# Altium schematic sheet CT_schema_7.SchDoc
size 391 x 238 mm
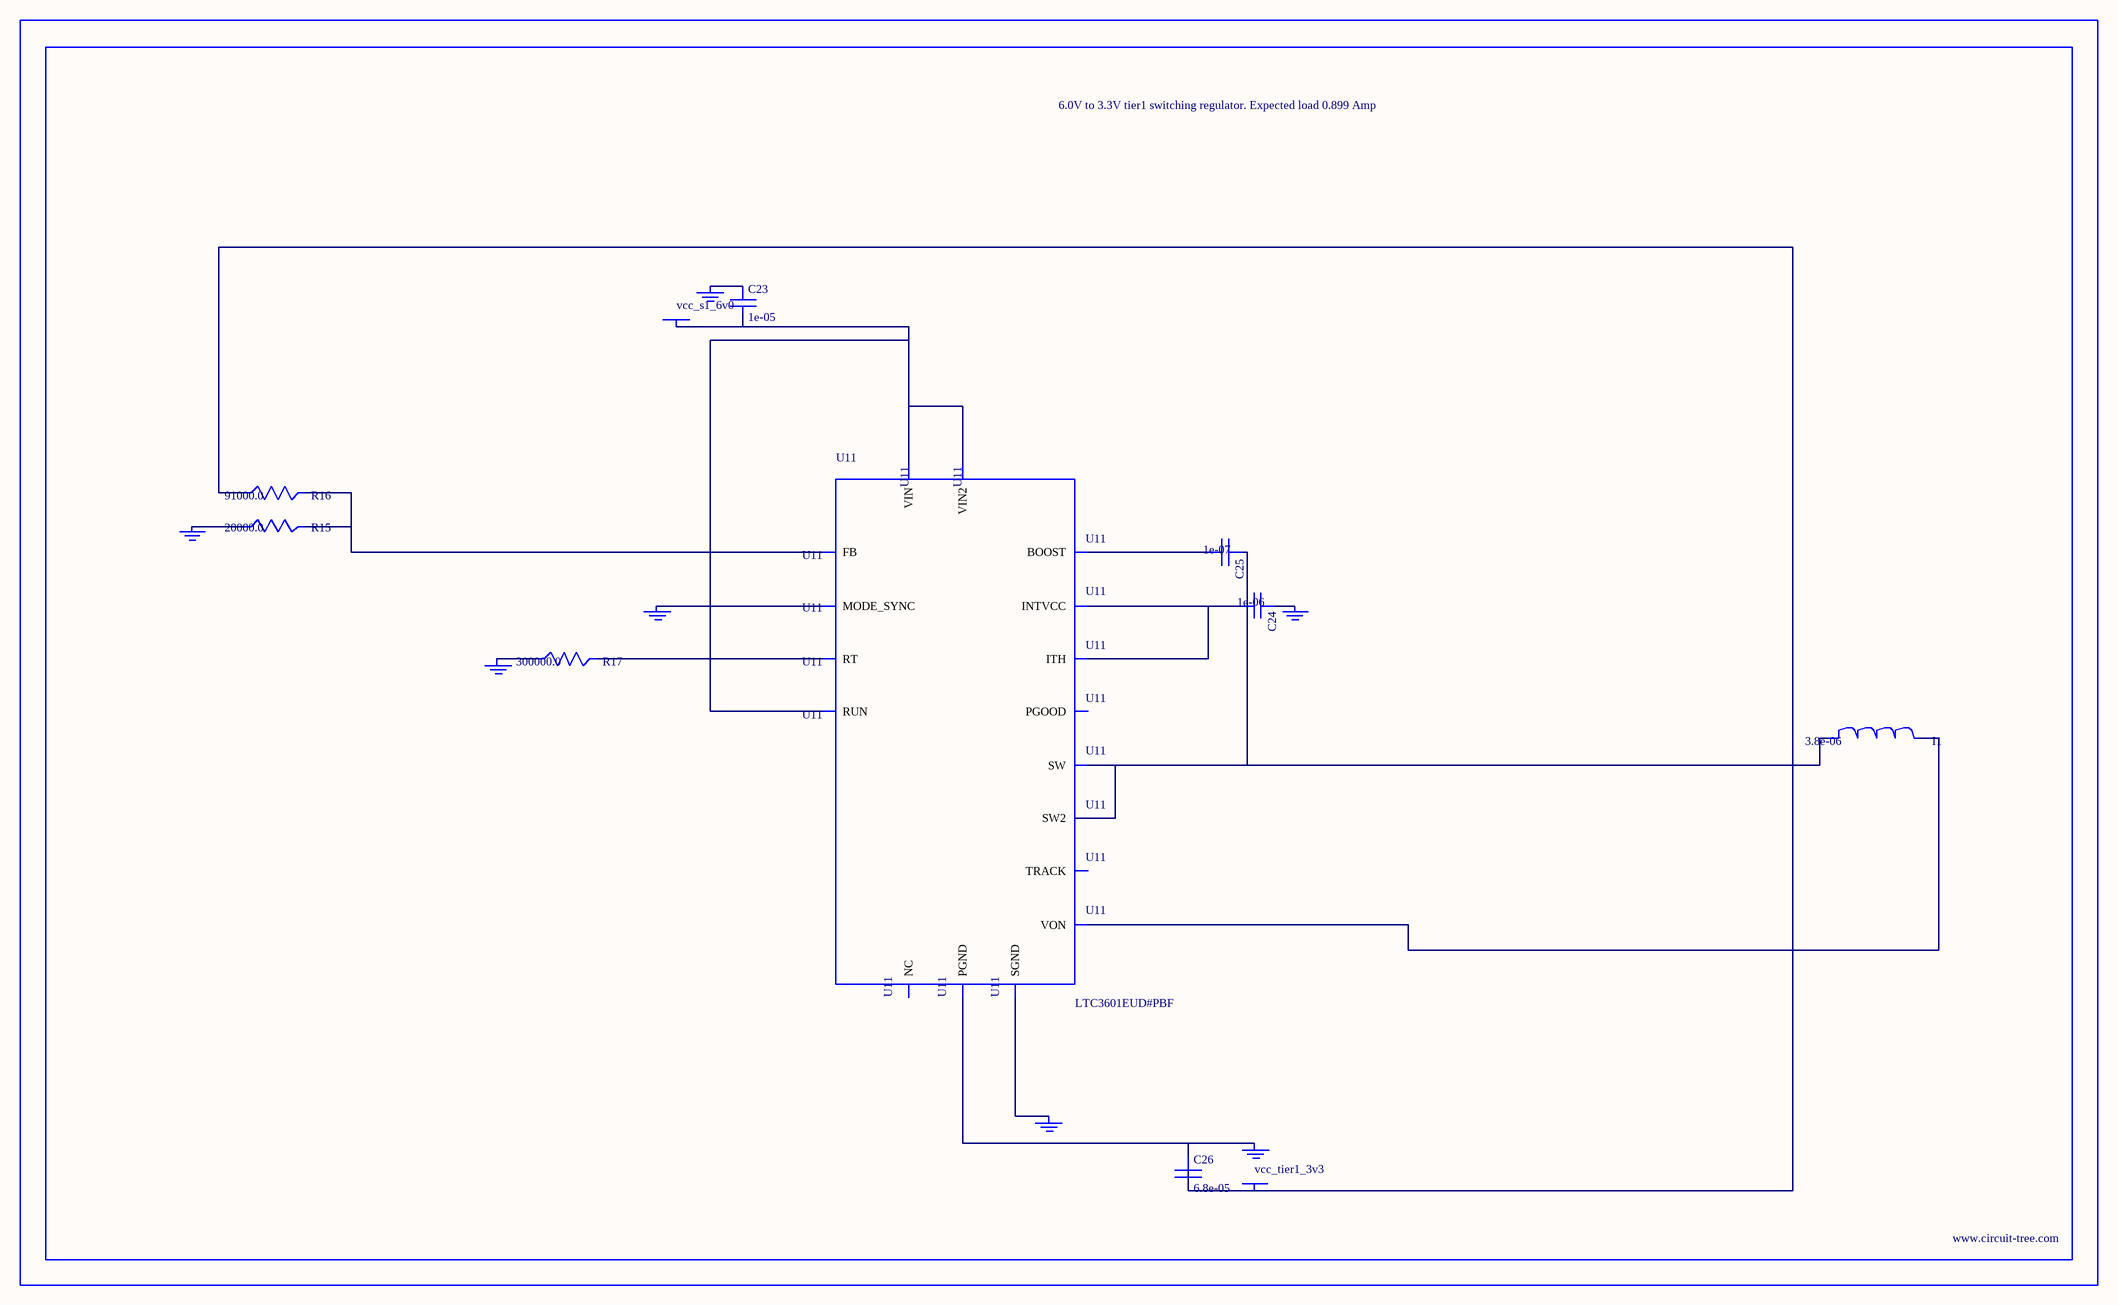
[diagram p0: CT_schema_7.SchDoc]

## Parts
BORDER6  (no value)
C23  1e-05  [C0805]
C24  1e-06  [C0603]
C25  1e-07  [C0402]
C26  6.8e-05  [2220]
GND_INSTANCE_6_0  (no value)
GND_INSTANCE_6_1  (no value)
GND_INSTANCE_6_2  (no value)
GND_INSTANCE_6_3  (no value)
GND_INSTANCE_6_4  (no value)
GND_INSTANCE_6_5  (no value)
GND_INSTANCE_6_6  (no value)
I1  3.8e-06  [DR1040]
POWER_INSTANCE_6_0  vcc_s1_6v0
POWER_INSTANCE_6_1  vcc_tier1_3v3
R15  20000.0  [R0603]
R16  91000.0  [R0603]
R17  300000.0  [R0603]
U11  LTC3601EUD#PBF  [QFN-16_EP]

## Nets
NetC23_1: C23.1 GND_INSTANCE_6_5.0(GND)
NetC23_2: C23.2 POWER_INSTANCE_6_0.0(PWR) U11.14(RUN) U11.15(VIN) U11.16(VIN2)
NetC24_1: C24.1 GND_INSTANCE_6_1.0(GND)
NetC24_2: C24.2 U11.7(INTVCC) U11.12(ITH)
NetC25_1: C25.1 I1.1 U11.3(SW) U11.4(SW2)
NetC25_2: C25.2 U11.6(BOOST)
NetC26_1: C26.1 GND_INSTANCE_6_6.0(GND) U11.17(PGND)
NetC26_2: C26.2 I1.2 POWER_INSTANCE_6_1.0(PWR) R16.1 U11.8(VON)
NetGND_INSTANCE_6_0_0: GND_INSTANCE_6_0.0(GND) U11.1(MODE_SYNC)
NetGND_INSTANCE_6_2_0: GND_INSTANCE_6_2.0(GND) U11.9(SGND)
NetGND_INSTANCE_6_3_0: GND_INSTANCE_6_3.0(GND) R17.1
NetGND_INSTANCE_6_4_0: GND_INSTANCE_6_4.0(GND) R15.1
NetR15_2: R15.2 R16.2 U11.11(FB)
NetR17_2: R17.2 U11.10(RT)

Not connected (* = marked no-connect by the designer): U11 2(PGOOD) 5(NC) 13(TRACK)

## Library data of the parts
BORDER6 = BORDER_PAGE6
C23 = C0805C106K8RACTU
C24 = C0603C105K3RACTU
C25 = C0402C104K3RACTU
C26 = C5750X5R1A686M
GND_INSTANCE_6_0-GND_INSTANCE_6_6 = GND
I1 = DR1040-3R8-R
POWER_INSTANCE_6_0 POWER_INSTANCE_6_1 = PWR
R15 = RC0603JR-0720KL
R16 = RC0603JR-0791KL
R17 = RC0603JR-07300KL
